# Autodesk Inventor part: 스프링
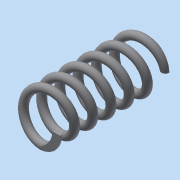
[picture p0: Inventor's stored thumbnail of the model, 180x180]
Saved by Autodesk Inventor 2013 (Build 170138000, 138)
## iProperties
Created: 2015-12
Part Number: 스프링
Material: 일반
Document SubType Name: Modeling
Designer: Administrator
Density: 1 g/cm^3
Mass: -0.0309104 g
Surface Area: 28.4714 cm^2
Volume: -0.0309104 cm^3
Author: Administrator
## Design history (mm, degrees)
sketch "스케치1"
  geometry: L1 (0, 0)-(0, 42); L2 (0, 42)-(8, 42); L3 (0, 0)-(8, 0); C1 r 1.5 at (8, 0)
  constraints: 6 end point, 1 centre point, 1 coincident, 1 parallel, 1 perpendicular, 1 vertical
  dimensions: "d0" = 42 distance of L1.start L1.end (derived); "d1" = 8 distance of L1.end L2.end; "d2" = 8 distance of L1.start L3.end; "d3" = 1.5 radius of C1
feature "코일1" sketch "스케치1" pitch "d4" = 10; turns "d6" = 6; dims "d5" = 41.99999 (computed from d0), "d7" = 0, angle "d8" = 90 deg, angle "d9" = 90 deg, "d10" = 0, "d11" = 0
sketch "스케치2"
  geometry: L1 (42, 15)-(0, 15); L2 (0, 15)-(0, -15); L3 (0, -15)-(42, -15); L4 (42, -15)-(42, 15); 2 further points
  constraints: 8 end point, 2 parallel, 1 coincident, 1 horizontal, 1 midpoint, 1 perpendicular
  dimensions: "d12" = 42 distance of L2.end L3.end (derived); "d14" = 30 distance of L3.end L1.start
extrude "돌출1" sketch "스케치2" stored distance "d15" = 10; taper "d16" = 0 deg
node "솔리드1"
